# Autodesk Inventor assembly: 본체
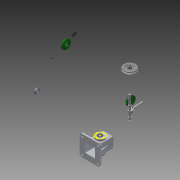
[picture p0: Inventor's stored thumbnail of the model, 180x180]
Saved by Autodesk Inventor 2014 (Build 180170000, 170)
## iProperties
Created: 2016-02
Part Number: 본체
Document SubType Name: Assembly
Designer: user
Author: user
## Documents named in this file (16)
- C:\Users\user\Desktop\460212V1001\본체.iam
- C:\Users\user\Desktop\460212V1001\본체1.ipt
- C:\Users\user\Desktop\460212V1001\편심축.ipt
- C:\Users\user\Desktop\460212V1001\뒤커버.ipt
- C:\Users\user\Desktop\460212V1001\V벨트풀리.ipt
- C:\Users\user\Desktop\460212V1001\고정핀 1.2 x 10.ipt
- C:\Users\user\Desktop\460212V1001\링크.ipt
- C:\Users\user\Desktop\460212V1001\멈춤나사 M3x8.ipt
- C:\Users\user\Desktop\460212V1001\베어링 12 x 32 x 10.ipt
- C:\Users\user\Desktop\460212V1001\볼트 M4 x 12.ipt
- C:\Users\user\Desktop\460212V1001\부시.ipt
- C:\Users\user\Desktop\460212V1001\슬라이드.ipt
- C:\Users\user\Desktop\460212V1001\앞커버.ipt
- C:\Users\user\Desktop\460212V1001\오일실 12 25 7.ipt
- C:\Users\user\Desktop\460212V1001\키 4 x 4 x 10.ipt
- C:\Users\user\Desktop\460212V1001\핀 5 x 18.ipt
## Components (4 placed, 4 different names)
1. V벨트풀리:1 — Mate:3
2. 고정핀 1.2 x 10:1
3. ISO 4762 M4 x 12:1
4. 핀 5 x 18:1 — Mate:10, Mate:11
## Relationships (3: Mate 3)
- Mate:3: V벨트풀리:1
- Mate:10: 핀 5 x 18:1
- Mate:11: 핀 5 x 18:1
